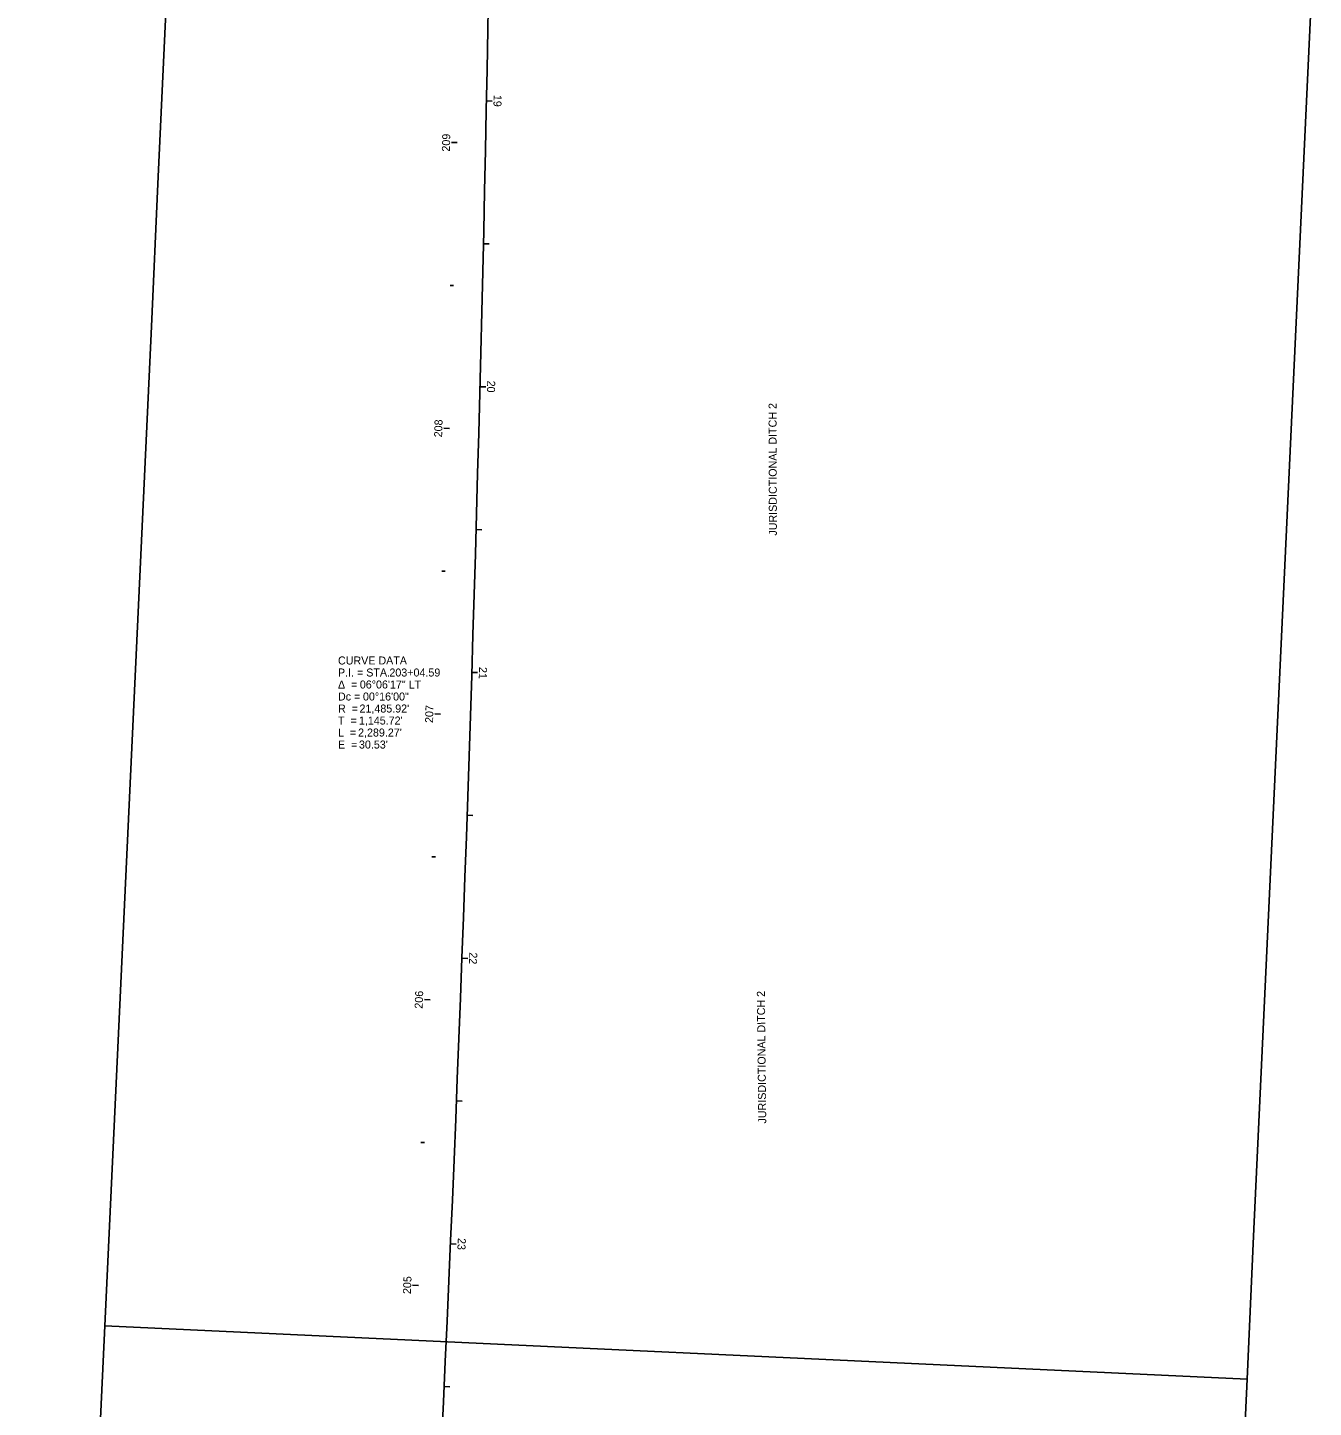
# Model space of a CAD drawing. Extents: x 172043 to 172958, y 249504 to 260295.
# Drawn here: x 172354.9 to 172804.8, y 257379.4 to 257862.1 of the extents above; entities that cross this region are included whole.
import ezdxf

# ---------------------------------------------------------------- set-up
doc = ezdxf.new("R2010")
doc.units = 0
for name, color, linetype in [('DR_X_Storm_Sewer', 7, 'Continuous'), ('LT_X_Poles', 7, 'Continuous'), ('PV_X_EOP', 7, 'Continuous'), ('RD_X_Fence', 7, 'Continuous'), ('SC_Scratch1', 7, 'Continuous')]:
    doc.layers.add(name, color=color, linetype=linetype)

msp = doc.modelspace()

# ---------------------------------------------------------------- linework, layer by layer
at = {"layer": 'DR_X_Storm_Sewer'}
for points in [[(172381.96, 257407.93), (172781.53, 257389.35), (172783.85, 257439.3), (172786.17, 257489.24), (172788.49, 257539.19), (172790.82, 257589.14), (172793.14, 257639.08), (172795.46, 257689.03), (172797.79, 257738.97), (172800.11, 257788.92), (172802.43, 257838.87), (172804.75, 257888.81), (172405.19, 257907.39), (172402.86, 257857.45), (172400.54, 257807.5), (172398.22, 257757.56), (172395.89, 257707.61), (172393.57, 257657.66), (172391.25, 257607.72), (172388.93, 257557.77), (172386.6, 257507.83), (172384.28, 257457.88)], [(172354.92, 256909.87), (172754.37, 256888.9), (172757.07, 256937.87), (172759.98, 256987.16), (172763.02, 257037.05), (172766.01, 257087.42), (172768.88, 257137.8), (172771.63, 257188.19), (172774.27, 257238.59), (172776.8, 257288.99), (172779.2, 257339.39), (172781.53, 257389.35), (172381.96, 257407.93), (172379.64, 257358), (172377.27, 257308.52), (172374.8, 257259.05), (172372.21, 257209.58), (172369.5, 257160.11), (172366.68, 257110.66), (172363.75, 257061.21), (172360.71, 257011.28), (172357.73, 256960.74)]]:
    msp.add_lwpolyline(points, close=True, dxfattribs=at)
at = {"layer": 'PV_X_EOP'}
for p, q in [((172505.23, 257821.88), (172503.23, 257821.93)), ((172503.94, 257771.9), (172502.74, 257771.93)), ((172502.53, 257721.92), (172500.53, 257721.98)), ((172501, 257671.94), (172499.8, 257671.98)), ((172499.36, 257621.97), (172497.36, 257622.04)), ((172497.6, 257572), (172496.4, 257572.05)), ((172495.73, 257522.04), (172493.73, 257522.12)), ((172493.74, 257472.08), (172492.54, 257472.13)), ((172491.63, 257422.12), (172489.63, 257422.21))]:
    msp.add_line(p, q, dxfattribs=at)
at = {"layer": 'SC_Scratch1'}
for p, q in [((172515.44, 257836.47), (172517.44, 257836.43)), ((172515.44, 257836.47), (172517.44, 257836.43)), ((172514.38, 257786.48), (172516.38, 257786.43)), ((172513.18, 257736.49), (172515.18, 257736.44)), ((172513.18, 257736.49), (172515.18, 257736.44)), ((172511.83, 257686.51), (172513.83, 257686.46)), ((172510.33, 257636.54), (172512.33, 257636.47)), ((172510.33, 257636.54), (172512.33, 257636.47)), ((172508.68, 257586.56), (172510.68, 257586.49)), ((172506.89, 257536.59), (172508.89, 257536.52)), ((172506.89, 257536.59), (172508.89, 257536.52)), ((172504.95, 257486.63), (172506.95, 257486.55)), ((172502.87, 257436.68), (172504.86, 257436.59)), ((172502.87, 257436.68), (172504.86, 257436.59)), ((172500.63, 257386.73), (172502.63, 257386.63))]:
    msp.add_line(p, q, dxfattribs=at)
msp.add_arc((155518.73, 258170.95), 17000, 354.099581, 0.195474, dxfattribs=at)
msp.add_arc((155518.73, 258170.95), 17000, 354.099581, 0.195474, dxfattribs=at)

# ---------------------------------------------------------------- texts
at = {"layer": 'LT_X_Poles'}
for rotation, p in [(90.1507, (172617.06, 257684.4)), (90.6262, (172613.35, 257478.75))]:
    msp.add_text('JURISDICTIONAL DITCH 2', height=2.8003, rotation=rotation, dxfattribs=at).set_placement(p)
at = {"layer": 'PV_X_EOP'}
for s, rotation, p in [('209', 88.5849, (172502.65, 257818.72)), ('208', 88.3182, (172499.93, 257718.75)), ('207', 88.0516, (172496.75, 257618.82)), ('206', 87.7849, (172493.1, 257518.88)), ('205', 87.5182, (172488.99, 257419.03))]:
    msp.add_text(s, height=2.8, rotation=rotation, dxfattribs=at).set_placement(p)
at = {"layer": 'RD_X_Fence'}
for s, p in [('CURVE DATA', (172463.51, 257639.32)), ('P.I. = STA. ', (172463.51, 257635.12)), ('203+04.59', (172481.5, 257635.12)), ('Δ  = ', (172463.51, 257630.92)), ('06°06\'17" LT', (172471.15, 257630.92)), ('Dc = ', (172463.51, 257626.72)), ('R  = ', (172463.51, 257622.52)), ("21,485.92'", (172471.04, 257622.52)), ('00°16\'00"', (172472.25, 257626.72)), ('T  = ', (172463.51, 257618.32)), ("1,145.72'", (172470.83, 257618.32)), ('L  = ', (172463.51, 257614.12)), ("2,289.27'", (172470.54, 257614.12)), ('E  = ', (172463.51, 257609.92)), ("30.53'", (172470.85, 257609.92))]:
    msp.add_text(s, height=2.8, dxfattribs=at).set_placement(p)
at = {"layer": 'SC_Scratch1'}
for s, rotation, p in [('19', 268.8726, (172517.98, 257838.62)), ('20', 268.5356, (172515.74, 257738.66)), ('21', 268.1985, (172512.89, 257638.49)), ('22', 267.8615, (172509.47, 257538.66)), ('23', 267.5245, (172505.46, 257438.72))]:
    msp.add_text(s, height=2.8, rotation=rotation, dxfattribs=at).set_placement(p)

doc.saveas('drawing.dxf')
